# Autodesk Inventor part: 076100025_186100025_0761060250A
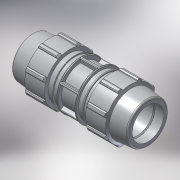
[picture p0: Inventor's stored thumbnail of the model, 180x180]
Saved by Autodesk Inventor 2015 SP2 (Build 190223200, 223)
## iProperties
Created: 2017-02
Part Number: 076100025_186100025_0761060250A
Material: PVC-Piping
Description: PLASSON REPAIR COUPLER 25
Document SubType Name: Modeling
Designer: KIM
Mass: 8658.36 g
Surface Area: 5623.3 cm^2
Volume: 6184.54 cm^3
Density: 1.4 g/cm^3
Appearance: Smooth - White
Author: KIM
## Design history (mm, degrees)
derived "07610.ipt"
feature "Solid1::07610.ipt"
tag "TaggingFeature1"
body "Solid1"
other parameters: "d1" = 136, "d2" = 25, "d4" = 11.33333, "d5" = 19.42857, "d7" = 54, "d8" = 40.5, "d9" = 19.42857, "d11" = 3.48571, "d12" = 43.2, "d13" = 120 deg, "d14" = 37.5, "d15" = 10 deg, "d16" = 48.6, "d18" = 1.25, "d19" = 35 deg, "d20" = 17.5 deg, "d21" = 50.22, "d23" = 0, "d25" = 360 deg, "d27" = 1.08, "d33" = 0.5, "d34" = 2.7, "d36" = 0, "d37" = 0.5, "d38" = 0.5, "d40" = 360 deg, "d42" = 24.48, "d43" = 1.62, "d46" = 0.75, "d50" = 4.47429, "d51" = 43.2, "d_" = 25, "E_" = 54, "H_" = 136, "d49" = 12.43429
